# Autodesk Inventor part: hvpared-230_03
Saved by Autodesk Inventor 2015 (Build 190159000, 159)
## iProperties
Created: 2020-08
Part Number: hvpared-230_03
Checked By: TraceParts S.A.
Material: Generic
Catalog Web Link: www.traceparts.com
Document SubType Name: Modeling
Designer: TraceParts
Density: 1 g/cm^3
Appearance: Default
Company: TraceParts S.A.
Author: TraceParts
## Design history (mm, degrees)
feature "hvpared-230_03.ipt"
body "Solid1"
